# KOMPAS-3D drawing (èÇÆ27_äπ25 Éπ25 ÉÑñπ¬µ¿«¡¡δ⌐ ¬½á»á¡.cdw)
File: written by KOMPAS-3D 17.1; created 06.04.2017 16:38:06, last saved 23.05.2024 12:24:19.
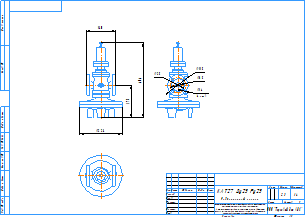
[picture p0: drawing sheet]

Sheet 1: A3, landscape

Title block, sheet 1: name: КАТ27 Ду25 Ру25 / Редукционный клапан; material: Сталь 20  ГОСТ 1050-88; mass: 23; sheets: 1; sheet format: A3; stored path: C:\Users\kka\KOMPAS_Work\!Trash\Редукционный клапан GP-2000\KOMPAS 2D\GP-2000 _ Ду40 Ру25 Редукционный клапан.cdw

Views: Вид 1
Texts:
  Klimkovich
  ADL
  Рама для чертежей
  Лит-Масса-Масштаб
  Материал-Предприятие
  Масштаб
  Изм.
  Лист
  № докум.
  Подп.
  Дата
  Лит.
  Разраб.
  Пров.
  Т.контр.
  Листов
  Внимание! Данный продукт является объектом авторского права ООО «Торговый Дом АДЛ».
  Запрещается изменение, копирование, распространение
  (в том числе путем копирования на другие сайты и ресурсы в Интернете)
  или любое иное использование информации и объектов без предварительного
  согласия правообладателя (ООО «Торговый Дом АДЛ»).
  Н.контр.
  Утв.
  ООО "Торговый дом АДЛ"
  Изменение
  Номер документа
  Подпись
  Обозначение документа
  Наименование изделия
  Масса изделия по ГОСТ 2.109-73
  Порядковый номер листа
  Общее количество листов в документе
  Характер работы, выполненной лицом, подписавшим документ
  Наименование или индекс предприятия, выпускающего документ
  Инв. № подл.
  Подп. и дата
  Взам. инв. №
  Инв. № дубл.
  Инвентарный номер подлинника по ГОСТ 2.501-68
  Подпись принявшего подлинник в отдел технической документации
  Инвентарный номер подлинника, взамен которого выпущен данный подлинник
  Инвентарный номер дубликата по ГОСТ 2.502-68
  Подпись принявшего дубликат в отдел технической документации
  Справ. №
  Перв. примен.
  Обозначение документа, взамен или на основании которого выпущен данный документ
  Обозначение документа, в котором впервые записан данный документ
  Подпись лица, копировавшего чертеж
  Обозначение формата листа
  !Рама для чертежа
Dimensions and other numbers on the sheet: 175; 404; 226; 160; 115; 85; 14; 4 отв.; 25; 1:4; 1; 23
